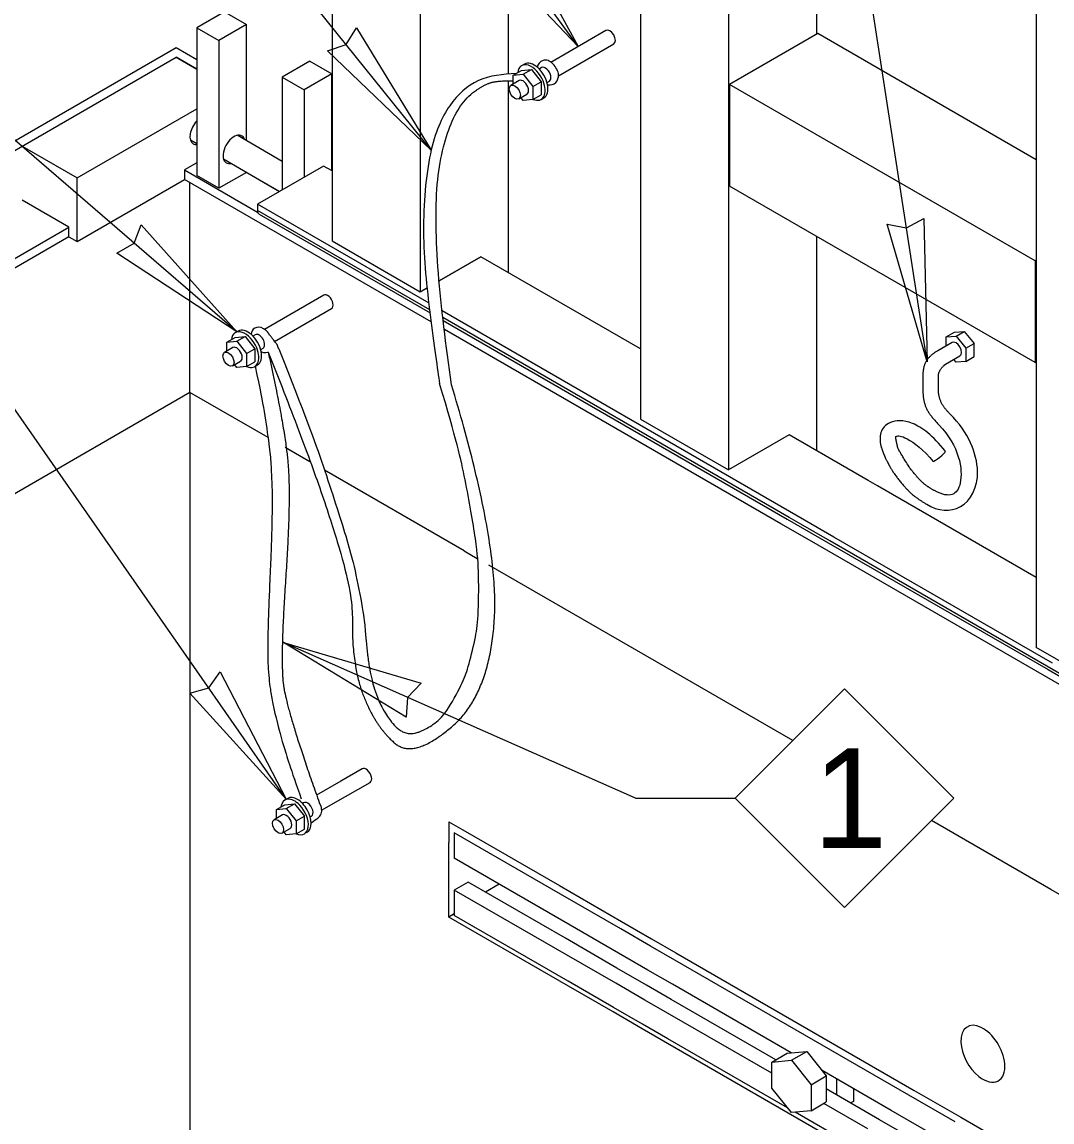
# Model space of a CAD drawing. Extents: x 99862 to 103151, y 100000 to 105076.
# Drawn here: x 101300.8 to 101466.2, y 101432.8 to 101609.4 of the extents above; entities that cross this region are included whole.
import ezdxf

# ---------------------------------------------------------------- set-up
doc = ezdxf.new("R2010")
doc.units = 0
for name, color, linetype in [('Level 10', 7, 'Continuous'), ('Level 11', 7, 'Continuous'), ('Level 15', 7, 'Continuous'), ('Level 2', 7, 'Continuous'), ('Level 20', 7, 'Continuous'), ('Level 3', 7, 'Continuous'), ('Level 4', 7, 'Continuous'), ('Level 5', 7, 'Continuous'), ('Level 8', 7, 'Continuous')]:
    doc.layers.add(name, color=color, linetype=linetype)

msp = doc.modelspace()

# ---------------------------------------------------------------- linework, layer by layer
at = {"layer": 'Level 10'}
for points, degree in [([(101386.96, 101600.86), (101386.9, 101601.44), (101386.17, 101602.87), (101384.35, 101603.62), (101383.57, 101602.5), (101383.51, 101602.14)], 3), ([(101380.13, 101601.1), (101378.04, 101601.02), (101373.76, 101600.5), (101369.28, 101596.44), (101366.03, 101589.3), (101364.85, 101575.64), (101366.25, 101562.43), (101367.56, 101553.3), (101367.85, 101551.36)], 3), ([(101385.19, 101599.29), (101385.73, 101599.19), (101386.63, 101599.48), (101386.99, 101600.49), (101386.96, 101600.86)], 3), ([(101369.77, 101551.15), (101368.85, 101557.52), (101367.35, 101569.68), (101367.03, 101584.05), (101369.45, 101593.74), (101372.04, 101597.29), (101373.79, 101598.44)], 3), ([(101373.79, 101598.44), (101375.27, 101599.45), (101377.33, 101599.95), (101379.69, 101599.94)], 2), ([(101339.59, 101560.13), (101339.14, 101560.45), (101337.99, 101560.42), (101337.64, 101559.62), (101337.61, 101559.22)], 3), ([(101340.6, 101559.08), (101340.34, 101559.51), (101339.98, 101559.9), (101339.59, 101560.13)], 2), ([(101342.03, 101556.93), (101341.89, 101557.3), (101341.73, 101557.72), (101340.6, 101559.08)], 2), ([(101340.34, 101556.39), (101340.32, 101556.38), (101339.98, 101556.2), (101339.59, 101556.25), (101339.23, 101556.42)], 3), ([(101340.34, 101556.39), (101343.14, 101543.71), (101343.98, 101532.36), (101342.31, 101507.8), (101343.15, 101499.12), (101348.55, 101484.06)], 2), ([(101340.34, 101556.39), (101354, 101522.31), (101353.69, 101506.04), (101357.69, 101496.08), (101363.78, 101491.02), (101376.02, 101501.62), (101377.33, 101526.16), (101369.77, 101551.15)], 2), ([(101342.03, 101556.93), (101346.29, 101546.31), (101349.21, 101538.19), (101353.27, 101525.51), (101354.4, 101520.95), (101355.73, 101514.01), (101355.93, 101511.62), (101356.14, 101509.24), (101356.18, 101508.8), (101356.27, 101507.95), (101356.32, 101507.54), (101356.49, 101506.35), (101356.61, 101505.61), (101357.02, 101503.56), (101357.35, 101502.4), (101358.1, 101500.39), (101358.51, 101499.53), (101359.4, 101498), (101359.89, 101497.3), (101360.84, 101496.19), (101361.32, 101495.78), (101362, 101495.4), (101362.22, 101495.3), (101362.68, 101495.18), (101362.92, 101495.15), (101363.45, 101495.15), (101363.74, 101495.18), (101364.42, 101495.36), (101364.8, 101495.49), (101366.84, 101496.5), (101368.91, 101498.31), (101371.56, 101503.36), (101372.38, 101505.44), (101373.64, 101510.47), (101374.08, 101513.45), (101374.19, 101520.92), (101373.84, 101525.4), (101372, 101536.14), (101370.56, 101542.32), (101367.85, 101551.36)], 3), ([(101338.25, 101554.12), (101339.09, 101550.21), (101339.68, 101547.02), (101340.56, 101541.13), (101340.79, 101538.56), (101340.95, 101534.85), (101340.97, 101533.64), (101340.97, 101531.14), (101340.95, 101529.85), (101340.86, 101525.85), (101340.74, 101523.04), (101340.51, 101517.5), (101340.39, 101514.76), (101340.31, 101511.59), (101340.29, 101510.96), (101340.27, 101509.75), (101340.27, 101509.15), (101340.27, 101507.39), (101340.3, 101506.22), (101340.48, 101503.78), (101340.63, 101502.51), (101341.12, 101499.72), (101341.45, 101498.22), (101342.71, 101493.39), (101343.9, 101489.62), (101345.66, 101484.65)], 3), ([(101348.93, 101482.71), (101348.93, 101483.16), (101348.79, 101483.64), (101348.55, 101484.06)], 2), ([(101347.25, 101480.83), (101348.33, 101481.57), (101348.68, 101481.86), (101348.92, 101482.34), (101348.93, 101482.71)], 3)]:
    msp.add_open_spline(points, degree=degree, dxfattribs=at)
at = {"layer": 'Level 11'}
for p, q in [((101370.21, 101479.22), (101370.21, 101475.13)), ((101387.27, 101469.37), (101370.21, 101479.22)), ((101387.77, 101464.99), (101370.21, 101475.13)), ((101372.42, 101471.31), (101370.21, 101470.03)), ((101388.04, 101462.29), (101372.42, 101471.31)), ((101370.21, 101470.03), (101370.21, 101465.95)), ((101388.25, 101459.62), (101370.21, 101470.03)), ((101377.43, 101470.97), (101375.22, 101469.69)), ((101385.03, 101470.66), (101385.03, 101470.66)), ((101396.94, 101463.78), (101387.27, 101469.37)), ((101388.49, 101455.4), (101370.21, 101465.95)), ((101396.56, 101459.92), (101387.77, 101464.99)), ((101396.33, 101457.5), (101388.04, 101462.29)), ((101401.72, 101461.02), (101396.94, 101463.78)), ((101405.64, 101458.76), (101401.72, 101461.02)), ((101396.12, 101455.07), (101388.25, 101459.62)), ((101401.29, 101457.19), (101396.56, 101459.92)), ((101443.19, 101437.08), (101405.64, 101458.76)), ((101401.04, 101454.78), (101396.33, 101457.5)), ((101405.26, 101454.9), (101401.29, 101457.19)), ((101395.78, 101451.19), (101388.49, 101455.4)), ((101400.8, 101452.37), (101396.12, 101455.07)), ((101405.03, 101452.48), (101401.04, 101454.78)), ((101424.31, 101443.9), (101405.26, 101454.9)), ((101404.82, 101450.05), (101400.8, 101452.37)), ((101421.81, 101442.79), (101405.03, 101452.48)), ((101400.44, 101448.49), (101395.78, 101451.19)), ((101421.17, 101440.61), (101404.82, 101450.05)), ((101404.51, 101446.15), (101400.44, 101448.49)), ((101423.71, 101435.06), (101404.51, 101446.15)), ((101440.34, 101434.65), (101429.25, 101441.05)), ((101438.48, 101433.17), (101429.93, 101438.11)), ((101450.61, 101432.8), (101443.19, 101437.08)), ((101433.41, 101429.46), (101424.92, 101434.36)), ((101436.57, 101431.72), (101429.53, 101435.78)), ((101447.67, 101430.41), (101440.34, 101434.65)), ((101445.76, 101428.96), (101438.48, 101433.17))]:
    msp.add_line(p, q, dxfattribs=at)
at = {"layer": 'Level 15'}
for p, q in [((101390.12, 101605.45), (101224.01, 101833.58)), ((101446.1, 101554.81), (101406.6, 101810.89)), ((101366.49, 101588.8), (101224.01, 101766.03)), ((101335.29, 101559.62), (101224.01, 101655.71)), ((101343.25, 101484.61), (101224.01, 101655.71)), ((101399.29, 101484.78), (101342.8, 101509.76)), ((101399.29, 101484.78), (101415.29, 101484.78))]:
    msp.add_line(p, q, dxfattribs=at)
for points in [[(101390.12, 101605.45), (101374.27, 101622.14), (101377.31, 101623.05), (101379.1, 101625.66)], [(101366.49, 101588.8), (101349.86, 101604.72), (101352.84, 101605.77), (101354.51, 101608.46)], [(101446.1, 101554.81), (101439.67, 101576.92), (101442.78, 101576.33), (101445.57, 101577.83)], [(101335.29, 101559.62), (101316.06, 101572.28), (101318.81, 101573.85), (101319.96, 101576.8)], [(101342.8, 101509.76), (101364.88, 101503.26), (101362.71, 101500.95), (101362.47, 101497.8)], [(101343.25, 101484.61), (101327.74, 101501.63), (101330.8, 101502.47), (101332.64, 101505.04)]]:
    msp.add_lwpolyline(points, close=True, dxfattribs=at)
at = {"layer": 'Level 2'}
for p, q in [((101327.78, 101549.89), (101327.78, 101324.7)), ((101369.33, 101481), (101369.33, 101477.64)), ((101369.33, 101481), (101371.59, 101479.69)), ((101371.59, 101479.69), (101387.08, 101470.75)), ((101369.33, 101465.69), (101369.33, 101477.64)), ((101387.08, 101470.75), (101397.06, 101464.99)), ((101370.21, 101466.2), (101369.33, 101465.69)), ((101388.52, 101454.61), (101369.33, 101465.69)), ((101397.06, 101464.99), (101401.86, 101462.22)), ((101401.86, 101462.22), (101405.76, 101459.97)), ((101405.76, 101459.97), (101444.05, 101437.86)), ((101395.71, 101450.46), (101388.52, 101454.61)), ((101400.38, 101447.76), (101395.71, 101450.46)), ((101404.46, 101445.41), (101400.38, 101447.76)), ((101432.8, 101429.05), (101404.46, 101445.41)), ((101444.05, 101437.86), (101451.51, 101433.56)), ((101451.51, 101433.56), (101458.65, 101429.43))]:
    msp.add_line(p, q, dxfattribs=at)
for start_param, end_param in [(4.031418, 7.111357), (0.828172, 2.177026), (2.177026, 4.031418)]:
    msp.add_ellipse((101455.06, 101443.75), major_axis=(-2.5, 4.33), ratio=0.57735, start_param=start_param, end_param=end_param, dxfattribs=at)
at = {"layer": 'Level 20'}
msp.add_lwpolyline([(101432.84, 101502.33), (101450.39, 101484.78), (101432.84, 101467.22), (101415.29, 101484.78)], close=True, dxfattribs=at)
at = {"layer": 'Level 3'}
for p, q in [((101154.1, 101506.26), (101325.57, 101605.26)), ((101325.57, 101605.26), (101328.89, 101603.35)), ((101327.78, 101549.89), (101327.78, 101583.57)), ((101327.78, 101549.89), (101204.48, 101478.71)), ((101340.32, 101542.66), (101327.78, 101549.89)), ((101347.03, 101538.79), (101343.05, 101541.08)), ((101371.79, 101524.49), (101349.38, 101537.43)), ((101371.79, 101524.49), (101373.9, 101523.27)), ((101404.06, 101505.85), (101375.76, 101522.2)), ((101424.54, 101494.03), (101404.06, 101505.85)), ((101465.99, 101470.1), (101446.8, 101481.18)), ((101474.05, 101465.44), (101465.99, 101470.1))]:
    msp.add_line(p, q, dxfattribs=at)
at = {"layer": 'Level 4'}
for p, q in [((101156.75, 101506.26), (101325.57, 101603.73)), ((101325.57, 101603.73), (101328.89, 101601.82)), ((101326.9, 101585.62), (101338.65, 101578.83)), ((101366.49, 101561.23), (101326.9, 101584.09)), ((101171.78, 101497.59), (101308.34, 101576.43)), ((101308.34, 101574.9), (101173.1, 101496.82)), ((101422.65, 101528.8), (101368.63, 101559.99)), ((101427.21, 101526.17), (101422.65, 101528.8)), ((101472.76, 101499.87), (101427.21, 101526.17)), ((101431.63, 101437.12), (101431.63, 101439.67)), ((101434.28, 101438.14), (101434.28, 101436.1)), ((101434.28, 101436.1), (101433.84, 101435.85))]:
    msp.add_line(p, q, dxfattribs=at)
at = {"layer": 'Level 5'}
for p, q in [((101350.59, 101738.52), (101350.59, 101574.23)), ((101364.73, 101730.36), (101364.73, 101566.07)), ((101378.87, 101722.19), (101378.87, 101601.01)), ((101400.09, 101709.94), (101400.09, 101545.62)), ((101414.23, 101702.8), (101414.23, 101537.46)), ((101463.63, 101673.25), (101463.63, 101542.16)), ((101428.37, 101632.63), (101428.37, 101607.42)), ((101333.31, 101611), (101328.89, 101608.45)), ((101333.31, 101611), (101336.84, 101608.96)), ((101336.84, 101608.96), (101332.42, 101606.41)), ((101336.84, 101590.31), (101336.84, 101608.96)), ((101328.89, 101608.45), (101328.89, 101584.72)), ((101328.89, 101608.45), (101332.42, 101606.41)), ((101428.55, 101607.53), (101414.4, 101599.36)), ((101463.63, 101587.27), (101428.55, 101607.53)), ((101332.42, 101606.41), (101332.42, 101582.68)), ((101328.89, 101601.82), (101325.57, 101603.73)), ((101347.01, 101603.09), (101342.59, 101600.54)), ((101347.01, 101603.09), (101350.54, 101601.05)), ((101342.59, 101600.54), (101342.59, 101582.43)), ((101342.59, 101600.54), (101346.12, 101598.5)), ((101350.54, 101601.05), (101346.12, 101598.5)), ((101350.54, 101585.49), (101350.54, 101601.05)), ((101346.12, 101598.5), (101346.12, 101584.47)), ((101378.87, 101599.91), (101378.87, 101569.13)), ((101463.46, 101571.04), (101414.4, 101599.36)), ((101414.4, 101599.36), (101414.4, 101583.03)), ((101309.66, 101584.34), (101328.89, 101595.44)), ((101342.59, 101586.99), (101335.34, 101591.18)), ((101300.83, 101589.44), (101309.66, 101584.34)), ((101327.85, 101590.45), (101328.89, 101589.85)), ((101328.89, 101586.76), (101326.9, 101585.62)), ((101333.16, 101587.39), (101342.17, 101582.18)), ((101349.22, 101586.25), (101338.61, 101580.13)), ((101350.59, 101585.46), (101349.22, 101586.25)), ((101309.66, 101574.13), (101309.66, 101584.34)), ((101326.9, 101585.62), (101326.9, 101584.09)), ((101332.42, 101582.68), (101328.89, 101584.72)), ((101336.84, 101585.23), (101332.42, 101582.68)), ((101336.84, 101585.23), (101336.84, 101585.26)), ((101342.15, 101582.17), (101336.84, 101585.23)), ((101309.66, 101574.13), (101326.9, 101584.09)), ((101463.46, 101554.71), (101414.4, 101583.03)), ((101308.34, 101576.43), (101300.83, 101580.77)), ((101366.16, 101564.23), (101338.61, 101580.13)), ((101338.61, 101580.13), (101338.61, 101579.11)), ((101366.27, 101563.14), (101338.61, 101579.11)), ((101338.87, 101578.54), (101366.32, 101562.69)), ((101308.34, 101574.9), (101308.34, 101576.43)), ((101308.34, 101574.9), (101309.66, 101574.13)), ((101350.59, 101574.23), (101364.73, 101566.07)), ((101428.37, 101574.97), (101428.37, 101540.55)), ((101367.79, 101567.83), (101374.46, 101571.68)), ((101374.46, 101571.65), (101367.79, 101567.8)), ((101400.09, 101556.88), (101374.46, 101571.68)), ((101463.63, 101571.14), (101463.46, 101571.04)), ((101463.46, 101571.04), (101463.46, 101554.71)), ((101364.73, 101566.07), (101365.9, 101566.75)), ((101426.43, 101529.43), (101368.26, 101563.01)), ((101423.98, 101529.82), (101368.37, 101561.93)), ((101368.43, 101561.47), (101423.66, 101529.58)), ((101463.46, 101554.71), (101463.63, 101554.81)), ((101400.09, 101545.62), (101414.23, 101537.46)), ((101423.98, 101543.09), (101414.23, 101537.46)), ((101436.66, 101535.77), (101423.98, 101543.09)), ((101463.63, 101542.16), (101463.63, 101532.6)), ((101438.12, 101534.92), (101436.66, 101535.77)), ((101463.63, 101520.2), (101438.12, 101534.92)), ((101463.63, 101532.6), (101463.63, 101508.97)), ((101423.66, 101529.58), (101430.23, 101525.79)), ((101425.84, 101528.75), (101423.98, 101529.82)), ((101431.16, 101526.7), (101426.43, 101529.43)), ((101430.5, 101526.06), (101425.84, 101528.75)), ((101472.94, 101501.55), (101430.5, 101526.06)), ((101466.25, 101506.44), (101431.16, 101526.7)), ((101430.23, 101525.79), (101465.52, 101505.42)), ((101473.12, 101503.49), (101463.63, 101508.97)), ((101465.52, 101505.42), (101472.9, 101501.15)), ((101421.17, 101442.42), (101423.63, 101443.84)), ((101423.63, 101443.84), (101426.78, 101444.12)), ((101424.32, 101442.7), (101426.78, 101444.12)), ((101426.78, 101444.12), (101429.93, 101440.2)), ((101421.17, 101442.42), (101424.32, 101442.7)), ((101421.17, 101438.22), (101421.17, 101442.42)), ((101424.32, 101442.7), (101427.47, 101438.78)), ((101427.47, 101438.78), (101429.93, 101440.2)), ((101429.93, 101440.2), (101429.93, 101436.01)), ((101424.32, 101434.3), (101421.17, 101438.22)), ((101427.47, 101438.78), (101427.47, 101434.59)), ((101427.47, 101434.59), (101429.93, 101436.01)), ((101427.47, 101434.59), (101424.32, 101434.3))]:
    msp.add_line(p, q, dxfattribs=at)
for centre, major_axis, start_param, end_param in [((101395.18, 101606.92), (0.63, -1.08), 6.283185, 9.424771), ((101395.18, 101606.92), (0.63, -1.08), 3.141586, 3.141593), ((101329.55, 101591.99), (-1.25, -2.17), 4.311388, 6.283191), ((101334.86, 101588.93), (1.25, 2.17), 5.777825, 9.42479), ((101329.55, 101591.99), (-1.25, -2.17), 0.000006, 0.401001), ((101334.86, 101588.93), (1.25, 2.17), 3.141605, 3.646953), ((101339.5, 101579.62), (-0.63, -1.08), 5.497787, 6.283185)]:
    msp.add_ellipse(centre, major_axis=major_axis, ratio=0.57735, start_param=start_param, end_param=end_param, dxfattribs=at)
at = {"layer": 'Level 8'}
for p, q in [((101394.56, 101608), (101385.69, 101602.89)), ((101386.96, 101600.73), (101395.81, 101605.84)), ((101381.48, 101602.62), (101381.02, 101602.36)), ((101384.23, 101602.04), (101383.85, 101601.82)), ((101379.69, 101600.84), (101381.01, 101601.61)), ((101379.69, 101600.84), (101381.26, 101600.98)), ((101379.69, 101599.42), (101379.69, 101600.84)), ((101381.01, 101601.61), (101382.58, 101601.75)), ((101381.26, 101600.98), (101382.58, 101601.75)), ((101381.26, 101600.98), (101382.83, 101599.02)), ((101382.58, 101601.75), (101384.16, 101599.79)), ((101380.63, 101599.97), (101379.31, 101599.2)), ((101382.83, 101599.02), (101384.16, 101599.79)), ((101382.83, 101599.02), (101382.83, 101596.93)), ((101384.16, 101599.79), (101384.16, 101597.69)), ((101385.1, 101599.66), (101385.48, 101599.88)), ((101380.56, 101597.04), (101381.88, 101597.8)), ((101381.26, 101596.79), (101380.9, 101597.23)), ((101382.83, 101596.93), (101381.26, 101596.79)), ((101382.83, 101596.93), (101384.16, 101597.69)), ((101384.15, 101596.94), (101384.61, 101597.21)), ((101349.26, 101565.52), (101339.74, 101560.03)), ((101341.38, 101558.09), (101350.51, 101563.36)), ((101335.52, 101559.76), (101335.06, 101559.49)), ((101449.18, 101558.81), (101450.51, 101559.57)), ((101450.51, 101559.57), (101452.08, 101559.71)), ((101450.75, 101558.95), (101452.08, 101559.71)), ((101452.08, 101559.71), (101453.65, 101557.75)), ((101333.72, 101557.98), (101335.05, 101558.74)), ((101333.72, 101557.98), (101335.3, 101558.12)), ((101333.72, 101556.55), (101333.72, 101557.98)), ((101335.05, 101558.74), (101336.62, 101558.88)), ((101335.3, 101558.12), (101336.62, 101558.88)), ((101335.3, 101558.12), (101336.87, 101556.16)), ((101336.62, 101558.88), (101338.2, 101556.92)), ((101338.27, 101559.18), (101337.89, 101558.96)), ((101450.13, 101557.93), (101447.81, 101556.59)), ((101449.18, 101558.81), (101450.75, 101558.95)), ((101449.18, 101557.38), (101449.18, 101558.81)), ((101450.75, 101558.95), (101452.33, 101556.99)), ((101452.33, 101556.99), (101453.65, 101557.75)), ((101453.65, 101555.65), (101453.65, 101557.75)), ((101334.67, 101557.1), (101333.35, 101556.34)), ((101336.87, 101556.16), (101338.2, 101556.92)), ((101336.87, 101556.16), (101336.87, 101554.06)), ((101338.2, 101556.92), (101338.2, 101554.83)), ((101339.14, 101556.79), (101339.54, 101557.03)), ((101452.33, 101556.99), (101452.33, 101554.89)), ((101334.6, 101554.17), (101335.92, 101554.94)), ((101335.3, 101553.92), (101334.94, 101554.37)), ((101336.87, 101554.06), (101338.2, 101554.83)), ((101338.19, 101554.08), (101338.64, 101554.34)), ((101449.06, 101554.43), (101451.38, 101555.76)), ((101450.75, 101554.75), (101450.39, 101555.2)), ((101452.33, 101554.89), (101450.75, 101554.75)), ((101452.33, 101554.89), (101453.65, 101555.65)), ((101336.87, 101554.06), (101335.3, 101553.92)), ((101445.42, 101552.45), (101445.42, 101550.66)), ((101447.92, 101550.66), (101447.92, 101552.45)), ((101355.44, 101489.48), (101352, 101487.49)), ((101352, 101487.49), (101348.12, 101485.26)), ((101352.75, 101485.04), (101356.69, 101487.32)), ((101341.68, 101482.96), (101343, 101483.73)), ((101343, 101483.73), (101344.58, 101483.87)), ((101343.47, 101484.74), (101343.02, 101484.47)), ((101343.25, 101483.1), (101344.58, 101483.87)), ((101344.58, 101483.87), (101346.15, 101481.91)), ((101346.03, 101484.05), (101345.84, 101483.94)), ((101348.92, 101482.83), (101352.75, 101485.04)), ((101342.63, 101482.08), (101341.3, 101481.32)), ((101341.68, 101482.96), (101343.25, 101483.1)), ((101341.68, 101481.54), (101341.68, 101482.96)), ((101343.25, 101483.1), (101344.83, 101481.14)), ((101344.83, 101481.14), (101346.15, 101481.91)), ((101346.15, 101479.81), (101346.15, 101481.91)), ((101344.83, 101481.14), (101344.83, 101479.04)), ((101342.55, 101479.15), (101343.88, 101479.92)), ((101343.25, 101478.9), (101342.89, 101479.35)), ((101344.83, 101479.04), (101343.25, 101478.9)), ((101344.83, 101479.04), (101346.15, 101479.81)), ((101346.6, 101479.33), (101346.18, 101479.09))]:
    msp.add_line(p, q, dxfattribs=at)
for centre, major_axis, ratio, start_param, end_param in [((101382.58, 101599.65), (1.56, -2.71), 0.57735, 1.342015, 3.794407), ((101383.04, 101599.91), (1.56, -2.71), 0.57735, 6.283145, 9.424778), ((101383.04, 101599.91), (1.56, -2.71), 0.57735, 3.141593, 3.141605), ((101384.85, 101600.96), (-0.63, 1.08), 0.57735, 3.141528, 6.283197), ((101381.26, 101598.88), (-0.63, 1.08), 0.57735, 3.141593, 6.283246), ((101382.58, 101599.65), (1.56, -2.71), 0.57735, 5.630371, 7.6252), ((101349.88, 101564.44), (0.63, -1.08), 0.57735, 6.283099, 9.424778), ((101349.88, 101564.44), (0.63, -1.08), 0.57735, 3.141593, 3.141605), ((101336.62, 101556.78), (1.56, -2.71), 0.57735, 1.342015, 3.794407), ((101337.08, 101557.05), (1.56, -2.71), 0.57735, 6.283177, 9.424778), ((101337.08, 101557.05), (1.56, -2.71), 0.57735, 3.141593, 3.141605), ((101338.89, 101558.09), (-0.63, 1.08), 0.57735, 4.712381, 6.283197), ((101338.89, 101558.09), (0.62, -1.08), 0.57735, 6.283174, 7.853989), ((101450.75, 101556.85), (0.62, -1.08), 0.57735, 6.283185, 9.424771), ((101450.75, 101556.85), (0.62, -1.08), 0.57735, 3.141586, 3.141595), ((101335.3, 101556.02), (-0.63, 1.08), 0.57735, 3.141509, 6.283185), ((101336.62, 101556.78), (1.56, -2.71), 0.57735, 5.630371, 7.6252), ((101338.89, 101558.09), (-0.63, 1.08), 0.57735, 3.141521, 3.18179), ((101448.92, 101545.55), (0.896, 0.872), 0.32788, 3.007699, 3.141593), ((101448.07, 101539.63), (0.969, 0.79), 0.091752, 3.1416, 6.283185), ((101448.07, 101539.63), (0.969, 0.79), 0.091752, 3.141593, 3.1416), ((101356.07, 101488.4), (-0.63, 1.08), 0.57735, 3.141586, 6.283197), ((101344.58, 101481.77), (1.56, -2.71), 0.57735, 1.978015, 3.794407), ((101345.04, 101482.03), (1.56, -2.71), 0.57735, 1.569482, 3.141626), ((101344.58, 101481.77), (-1.56, 2.71), 0.57735, 2.488778, 5.119607), ((101346.66, 101482.97), (0.63, -1.08), 0.57735, 5.994979, 9.424782), ((101343.25, 101481), (-0.63, 1.08), 0.57735, 3.141593, 6.283246), ((101344.58, 101481.77), (1.56, -2.71), 0.57735, 1.573887, 1.575599), ((101344.58, 101481.77), (1.56, -2.71), 0.57735, 1.570797, 1.571274), ((101345.04, 101482.03), (-1.56, 2.71), 0.57735, 3.14156, 4.711073)]:
    msp.add_ellipse(centre, major_axis=major_axis, ratio=ratio, start_param=start_param, end_param=end_param, dxfattribs=at)
for centre in [(101379.93, 101598.12), (101333.97, 101555.25), (101341.93, 101480.24)]:
    msp.add_ellipse(centre, major_axis=(0.63, -1.08), ratio=0.57735, dxfattribs=at)
for points, degree in [([(101447.81, 101556.59), (101446.46, 101555.82), (101445.41, 101554), (101445.42, 101552.45)], 2), ([(101447.92, 101552.45), (101447.88, 101552.98), (101448.64, 101554.16), (101449.06, 101554.43)], 2), ([(101445.42, 101550.66), (101445.41, 101548.65), (101446.47, 101546.27), (101448.02, 101544.68)], 2), ([(101449.81, 101546.43), (101448.7, 101547.53), (101447.89, 101549.42), (101447.92, 101550.66)], 2), ([(101449.04, 101540.42), (101447.01, 101543.01), (101443.53, 101545.63), (101439.81, 101545.32), (101438.47, 101543.53), (101438.51, 101542.07), (101438.67, 101541.36)], 3), ([(101446.04, 101531.97), (101447.85, 101530.84), (101451.85, 101530.47), (101455.5, 101536.59), (101452.74, 101543.5), (101449.81, 101546.43)], 3), ([(101448.02, 101544.68), (101449.6, 101543.05), (101451.62, 101539.45), (101451.64, 101534.89), (101450.36, 101533.21), (101448.62, 101533.43), (101447.29, 101534.14)], 3), ([(101441.1, 101542.41), (101441.1, 101542.59), (101441.13, 101542.9), (101441, 101542.82), (101442.31, 101543.13), (101445.59, 101540.64), (101447.1, 101538.84)], 3), ([(101443.35, 101537.75), (101441.51, 101540.68), (101441.35, 101541.22), (101441.1, 101542.41)], 2), ([(101438.67, 101541.36), (101438.93, 101540.57), (101439.15, 101539.98), (101439.39, 101539.44)], 2), ([(101439.39, 101539.44), (101439.89, 101538.43), (101439.92, 101538.38), (101440.51, 101537.37)], 2), ([(101440.51, 101537.37), (101440.55, 101537.3), (101440.6, 101537.22), (101441.4, 101536.1)], 2), ([(101447.29, 101534.14), (101445.99, 101534.86), (101444.52, 101536.27), (101443.35, 101537.75)], 2), ([(101441.4, 101536.1), (101442.75, 101534.41), (101444.46, 101532.88), (101446.04, 101531.97)], 2)]:
    msp.add_open_spline(points, degree=degree, dxfattribs=at)

# ---------------------------------------------------------------- texts
at = {"layer": 'Level 20'}
msp.add_text('1', height=16, dxfattribs=at).set_placement((101427.81, 101476.78))

doc.saveas('drawing.dxf')
